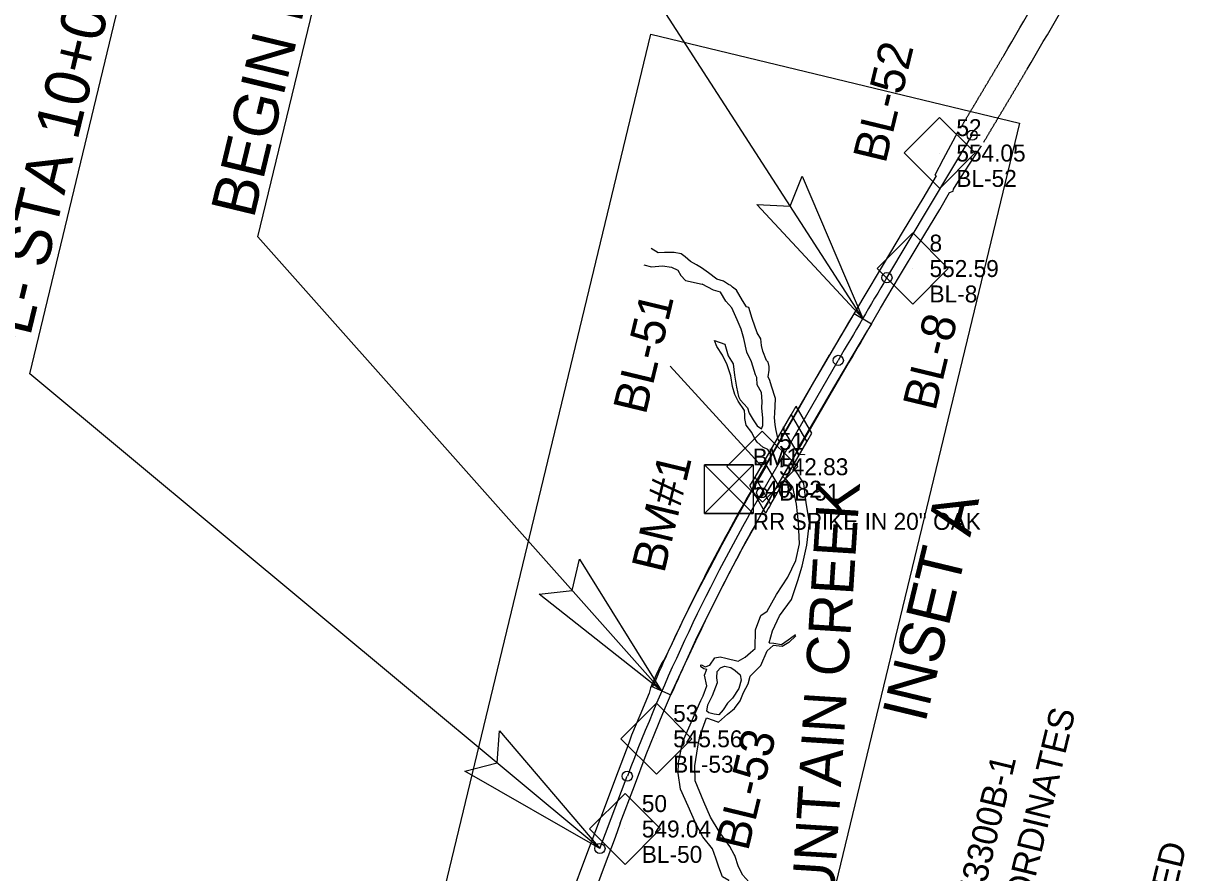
# Model space of a CAD drawing. Extents: x 1649669 to 1659218, y 588594 to 607900.
# Drawn here: x 1652859 to 1654231, y 597539 to 598543 of the extents above; entities that cross this region are included whole.
import ezdxf

# ---------------------------------------------------------------- set-up
doc = ezdxf.new("R2010")
doc.units = 0
for name, color, linetype in [('CTL Bench Mark CELL', 7, 'Continuous'), ('CTL Bench Mark Cogo Comment', 7, 'Continuous'), ('CTL Bench Mark Cogo Elevation', 7, 'Continuous'), ('CTL Bench Mark Cogo Number', 7, 'Continuous'), ('CTL Bench Mark Text', 7, 'Continuous'), ('CTL NGS Horizontal Text', 7, 'Continuous'), ('CTL Supplemental Horizontal and Vertical CELL', 7, 'Continuous'), ('CTL Supplemental Horizontal and Vertical Cogo Comment', 7, 'Continuous'), ('CTL Supplemental Horizontal and Vertical Cogo Elevation', 7, 'Continuous'), ('CTL Supplemental Horizontal and Vertical Cogo Number', 7, 'Continuous'), ('CTL Supplemental Horizontal and Vertical Leader', 7, 'Continuous'), ('CTL Supplemental Horizontal and Vertical Text', 7, 'Continuous'), ('Default', 7, 'Continuous'), ('Exist Hydro Jurisdictional Stream or Body of Water', 7, 'Continuous'), ('Exist Hydro Stream or Body of Water', 7, 'Continuous'), ('Exist Roads EOP', 7, 'Continuous'), ('Exist Structure Major Bridge WW', 7, 'Continuous'), ('Exist Structure Major Deck Tunnel Box Culvert', 7, 'Continuous'), ('Old_Level_20', 7, 'Continuous'), ('Old_Level_3', 7, 'Continuous'), ('Prop EOT', 7, 'Continuous'), ('Prop Horizontal Alignment', 7, 'Continuous'), ('Prop Horizontal Alignment Station Label', 7, 'Continuous'), ('Prop Terminator CELL', 7, 'Continuous'), ('Sheet Cutting Line CELL', 7, 'Continuous'), ('Sheet Data Field CELL', 7, 'Continuous')]:
    doc.layers.add(name, color=color, linetype=linetype)

msp = doc.modelspace()

# ---------------------------------------------------------------- linework, layer by layer
at = {"layer": 'CTL Bench Mark CELL'}
msp.add_line((1653692.9, 597992.3), (1653692.9, 597992.3), dxfattribs=at)
msp.add_lwpolyline([(1653664.1, 598021), (1653721.6, 598021), (1653721.6, 597963.5), (1653664.1, 597963.5)], close=True, dxfattribs=at)
for points in [[(1653721.6, 598021), (1653664.1, 597963.5), (1653692.9, 597992.2), (1653721.6, 597963.5), (1653664.1, 598021)], [(1653692.9, 597992.2), (1653721.6, 598021), (1653664.1, 598021), (1653692.9, 597992.2)], [(1653692.9, 597992.2), (1653664.1, 597963.5), (1653721.6, 597963.5), (1653692.9, 597992.2)]]:
    msp.add_lwpolyline(points, dxfattribs=at)
at = {"layer": 'CTL Supplemental Horizontal and Vertical CELL'}
for p, q in [((1653941.5, 598389.3), (1653941.5, 598389.3)), ((1653909.8, 598252.9), (1653909.8, 598252.9)), ((1653732.1, 598018.8), (1653732.1, 598018.8)), ((1653607, 597697.5), (1653607, 597697.5)), ((1653570, 597591), (1653570, 597591))]:
    msp.add_line(p, q, dxfattribs=at)
for points in [[(1653899.8, 598389.5), (1653941.7, 598431.4), (1653983.7, 598389.4), (1653941.8, 598347.5)], [(1653868, 598253), (1653910, 598295), (1653952, 598253), (1653910, 598211)], [(1653690.4, 598018.9), (1653732.3, 598060.9), (1653774.3, 598018.9), (1653732.4, 597976.9)], [(1653565.3, 597697.6), (1653607.2, 597739.6), (1653649.2, 597697.6), (1653607.3, 597655.6)], [(1653528.3, 597591.1), (1653570.2, 597633), (1653612.2, 597591), (1653570.3, 597549.1)]]:
    msp.add_lwpolyline(points, close=True, dxfattribs=at)
at = {"layer": 'CTL Supplemental Horizontal and Vertical Leader'}
msp.add_lwpolyline([(1653732.1, 598018.8), (1653623.5, 598137.5)], dxfattribs=at)
at = {"layer": 'Default'}
for p, q in [((1653136.5, 598290.4), (1653329, 599087.7)), ((1653850.9, 598193.8), (1653425.8, 598852.2)), ((1652867, 598128.7), (1653023.1, 598775.4)), ((1653612.7, 597754.5), (1653136.5, 598290.4)), ((1653540.5, 597567.9), (1652867, 598128.7))]:
    msp.add_line(p, q, dxfattribs=at)
at = {"layer": 'Exist Hydro Jurisdictional Stream or Body of Water'}
for points in [[(1653668.8, 598247.7), (1653660.4, 598253.7), (1653654.5, 598257.1), (1653647.4, 598261.4), (1653641.1, 598266.7), (1653636.3, 598270.3), (1653628.2, 598271.7), (1653616.9, 598271.7), (1653609.4, 598271.5), (1653601.2, 598276.4)], [(1653592.2, 598257.3), (1653601.6, 598254.8), (1653614.5, 598256.1), (1653625.2, 598254.5), (1653632.5, 598251.1), (1653636.2, 598244.7), (1653641.6, 598238.9), (1653661.4, 598234.3)], [(1653739.3, 598142.3), (1653737.1, 598144.2), (1653732.8, 598155.3), (1653731.3, 598161.9), (1653730.4, 598169.8), (1653726.1, 598176.9), (1653720.3, 598193.7), (1653716.5, 598207), (1653713.8, 598207.6), (1653708.8, 598215.1), (1653701.7, 598227.2), (1653697.2, 598231), (1653695.2, 598232.9), (1653692.2, 598233.9), (1653686.5, 598237.8), (1653678.5, 598240.3), (1653668.8, 598247.7)], [(1653724.3, 598127.5), (1653719.5, 598142.7), (1653714.2, 598154.2), (1653710.3, 598170.1), (1653707.2, 598181.3), (1653702.5, 598192.5), (1653696.3, 598206.5), (1653689.4, 598214.3), (1653683.1, 598225.1), (1653674.5, 598227.4), (1653661.4, 598234.3)], [(1653714.7, 598088.5), (1653716.6, 598082.1), (1653721.3, 598074.1), (1653726.4, 598067), (1653731.2, 598063.6), (1653732.9, 598067.7), (1653733, 598076.1), (1653731.6, 598088.3), (1653732.1, 598095.9), (1653731.5, 598106.6), (1653726.4, 598115.7), (1653725.8, 598124.4), (1653724.3, 598127.5)], [(1653752.6, 598048.3), (1653751.1, 598051), (1653748.6, 598061.5), (1653747.5, 598068.2), (1653746.7, 598076.9), (1653747.2, 598081.7), (1653748, 598099.4), (1653743.3, 598114.1), (1653741.1, 598120.6)], [(1653743.2, 598031.5), (1653741.8, 598033.9), (1653738.9, 598039), (1653733.1, 598041.9), (1653726.3, 598048), (1653722.6, 598053.2), (1653719.9, 598059.4), (1653713.2, 598067.9), (1653711.6, 598075.7), (1653711.8, 598079.7), (1653711.1, 598085.3)], [(1653740.5, 597810.8), (1653744.5, 597825.2), (1653752.7, 597842.9), (1653766.9, 597862.1), (1653774.2, 597884.6), (1653779.2, 597901.2), (1653784.8, 597926.2), (1653788.2, 597953), (1653784.2, 597976.2), (1653781.5, 597999.1), (1653770, 598016.7), (1653766, 598023.9)], [(1653703.8, 597789.2), (1653712, 597793.9), (1653718.2, 597799.4), (1653723.7, 597804.1), (1653724.2, 597826.1), (1653730.4, 597843.3), (1653737.9, 597848.4), (1653749, 597867.9), (1653762.5, 597888.2), (1653771.7, 597908), (1653776.1, 597927.8), (1653775.2, 597952.4), (1653772.6, 597974.7), (1653768.4, 597994.5), (1653761, 598003.5), (1653757.3, 598006.3), (1653756.6, 598007.5)], [(1653717.8, 597771.3), (1653730.5, 597783.9), (1653737.9, 597801.3)], [(1653659.4, 597784.6), (1653659.2, 597783.4), (1653663.1, 597780.7), (1653666.7, 597779.7)], [(1653659.4, 597784.6), (1653660.3, 597784.7), (1653664.8, 597782.3), (1653670.2, 597784.3)], [(1653670.2, 597784.3), (1653676.3, 597793), (1653682.4, 597794.4), (1653689.4, 597792.6), (1653703.8, 597789.2)], [(1653638.4, 597694.5), (1653659.6, 597742.6), (1653662.6, 597748.1), (1653666.7, 597759.9), (1653664.1, 597772.6), (1653666.7, 597779.7)], [(1653666.8, 597730.2), (1653668.1, 597737.6), (1653673.5, 597748.5), (1653679.4, 597764.1), (1653678.5, 597769.4), (1653679.1, 597776.9), (1653682.8, 597781.3), (1653687.7, 597783.3), (1653695.3, 597781.9), (1653700.4, 597778.2), (1653706.2, 597773.2)], [(1653693.8, 597570.3), (1653681.5, 597588.1), (1653671, 597605.1), (1653663.1, 597623.2), (1653653, 597647.9), (1653652.7, 597665.5), (1653656.2, 597688.2), (1653658.3, 597700.5), (1653666.3, 597722.4)], [(1653673.4, 597567.6), (1653662.2, 597581.7), (1653653.5, 597598.1), (1653644.9, 597618), (1653635.8, 597638.1), (1653632.9, 597656.9), (1653633.3, 597669.7), (1653638.4, 597694.5)], [(1653730.3, 597338.1), (1653733.3, 597360.2), (1653735.6, 597380.6), (1653726.8, 597413.4), (1653724.7, 597422.1), (1653718.3, 597439.8), (1653719.4, 597456.6), (1653714.6, 597471.9), (1653709.4, 597485), (1653703.2, 597498.6), (1653701.5, 597506), (1653695.8, 597517.3), (1653692.9, 597530.2), (1653685.3, 597534.3), (1653681, 597546), (1653677.2, 597556.7), (1653673.4, 597567.6)], [(1653748.4, 597343.1), (1653752.9, 597375.2), (1653752.5, 597388.1), (1653747.3, 597414.1), (1653745.8, 597424.3), (1653743.5, 597437.2), (1653740.3, 597449.2), (1653740, 597455.8), (1653734.8, 597464.4), (1653730.6, 597471.8), (1653727.7, 597497.5), (1653726.4, 597508.9), (1653723.9, 597520.6), (1653716.2, 597528.4), (1653709.3, 597536.5), (1653704.3, 597546.2), (1653699.9, 597559.6), (1653699.1, 597561), (1653693.8, 597570.3)]]:
    msp.add_lwpolyline(points, dxfattribs=at)
at = {"layer": 'Exist Hydro Stream or Body of Water'}
for points in [[(1653676, 598167.9), (1653688.1, 598163.7), (1653691.8, 598149.9), (1653698, 598140.2), (1653699.4, 598127), (1653702, 598112.9), (1653704.1, 598101.8), (1653706.2, 598098), (1653714.7, 598088.5)], [(1653711.1, 598085.3), (1653703.7, 598096.4), (1653699.8, 598104.3), (1653697.2, 598113.7), (1653695.1, 598126), (1653690.7, 598139.3), (1653685.1, 598150.4), (1653678.4, 598160.7), (1653676, 598167.9)], [(1653741.1, 598120.6), (1653739.1, 598125.1), (1653740.2, 598132.9), (1653740.3, 598137.3), (1653739.3, 598142.3)], [(1653771.8, 597819.1), (1653763.7, 597811.4), (1653755.8, 597806.7), (1653745.1, 597807.8), (1653737.9, 597801.3)], [(1653740.5, 597810.8), (1653745.8, 597810.3), (1653755, 597809), (1653762.9, 597814.5), (1653771.5, 597820.5)], [(1653706.2, 597773.2), (1653707.3, 597766.6), (1653704.4, 597757.1), (1653696.9, 597745.3), (1653691.1, 597739.4), (1653685.9, 597731.6), (1653681.1, 597725.9), (1653675.3, 597726.5), (1653669.2, 597728.2), (1653666.8, 597730.2)], [(1653699.3, 597733.4), (1653706.2, 597742.2), (1653709.9, 597752.2), (1653715.6, 597762.4), (1653717.8, 597771.3)], [(1653666.3, 597722.4), (1653674.4, 597719.5), (1653680.7, 597717.3), (1653691.1, 597726.4), (1653697, 597731.5), (1653699.3, 597733.4)]]:
    msp.add_lwpolyline(points, dxfattribs=at)
at = {"layer": 'Exist Roads EOP'}
for points in [[(1653963.2, 598414.5), (1653946.1, 598382.2), (1653936.1, 598363.3), (1653937.6, 598362.4), (1653921.9, 598335.5), (1653898.6, 598297.3), (1653875, 598257.8), (1653851, 598217.6), (1653836.5, 598192.6), (1653818.8, 598162.7), (1653796.3, 598124.5), (1653774.3, 598085.7), (1653760, 598060.8), (1653759, 598059.6)], [(1653773.1, 598036.4), (1653773.1, 598036.7), (1653772.7, 598037.2), (1653794.4, 598073.8), (1653816.9, 598112.3), (1653839.5, 598150.8), (1653856.9, 598180.3), (1653871.8, 598206), (1653894.4, 598243.9), (1653917.4, 598282.6), (1653942, 598322.8), (1653953.2, 598342.5), (1653957.8, 598344.4), (1653958, 598346.5), (1653959.3, 598348.6), (1653971.1, 598367.1), (1653991, 598397.8)], [(1653736.9, 598020.2), (1653736.6, 598019), (1653719.2, 597989.2), (1653700.6, 597956.1), (1653684.6, 597926.7), (1653670.3, 597899.6), (1653655.3, 597871), (1653640.4, 597841.4), (1653625.6, 597809.6), (1653616.4, 597790.9), (1653615.5, 597790.1), (1653613.4, 597786.4), (1653606.9, 597772.9), (1653600.4, 597757.8), (1653598.6, 597751.5), (1653587.8, 597725.2), (1653577.7, 597701.6), (1653574.8, 597692.2), (1653559, 597651), (1653542.1, 597605.7)], [(1653564.5, 597597.7), (1653581.2, 597642.1), (1653595.3, 597679), (1653605.2, 597704.2), (1653614.9, 597727.4), (1653626, 597753.2), (1653641, 597786.5), (1653655.9, 597818.7), (1653671.7, 597850.9), (1653688.4, 597883.5), (1653707.1, 597919), (1653720.7, 597943.7), (1653734.9, 597970.1), (1653749.8, 597996.4), (1653750.8, 597997.3)], [(1653472.3, 597421.4), (1653481.4, 597445.1), (1653491.5, 597471.6), (1653506.4, 597511.5), (1653524.9, 597561.2), (1653542.1, 597605.7)], [(1653564.5, 597597.7), (1653558.4, 597580.8), (1653545.6, 597546.8), (1653529.7, 597504), (1653515.6, 597467.4), (1653493.8, 597408.8)]]:
    msp.add_lwpolyline(points, dxfattribs=at)
for radius in [8984, 9016]:
    msp.add_arc((1646280.4, 603070.7), radius, 329.45173, 330.4149, dxfattribs=at)
for points in [[(1653966.3, 598418.6), (1653967, 598419.8), (1653967.7, 598420.9), (1653968.4, 598422.1), (1653969.1, 598423.2), (1653969.8, 598424.4), (1653970.5, 598425.6), (1653971.2, 598426.7), (1653971.9, 598427.9), (1653972.6, 598429), (1653973.3, 598430.2), (1653974, 598431.4), (1653974.7, 598432.5), (1653975.4, 598433.7), (1653976.1, 598434.8), (1653976.7, 598436), (1653977.4, 598437.2), (1653978.1, 598438.3), (1653978.8, 598439.5), (1653979.5, 598440.6), (1653980.2, 598441.8), (1653980.9, 598443), (1653981.6, 598444.1), (1653982.3, 598445.3), (1653983, 598446.4), (1653983.7, 598447.6), (1653984.4, 598448.8), (1653985.1, 598449.9), (1653985.7, 598451.1), (1653986.4, 598452.2), (1653987.1, 598453.4), (1653987.8, 598454.6), (1653988.5, 598455.7), (1653989.2, 598456.9), (1653989.9, 598458), (1653990.6, 598459.2), (1653991.3, 598460.4), (1653992, 598461.5), (1653992.7, 598462.7), (1653993.4, 598463.8), (1653994, 598465), (1653994.7, 598466.2), (1653995.4, 598467.3), (1653996.1, 598468.5), (1653996.8, 598469.6), (1653997.5, 598470.8), (1653998.2, 598472), (1653998.9, 598473.1), (1653999.6, 598474.3), (1654000.3, 598475.4), (1654000.9, 598476.6), (1654001.6, 598477.8), (1654002.3, 598478.9), (1654003, 598480.1), (1654003.7, 598481.2), (1654004.4, 598482.4), (1654005.1, 598483.6), (1654005.8, 598484.7), (1654006.5, 598485.9), (1654007.1, 598487), (1654007.8, 598488.2), (1654008.5, 598489.4), (1654009.2, 598490.5), (1654009.9, 598491.7), (1654010.6, 598492.8), (1654011.3, 598494), (1654012, 598495.2), (1654012.6, 598496.3), (1654013.3, 598497.5), (1654014, 598498.6), (1654014.7, 598499.8), (1654015.4, 598501), (1654016.1, 598502.1), (1654016.8, 598503.3), (1654017.4, 598504.5)], [(1653993.8, 598402.2), (1653994.5, 598403.3), (1653995.2, 598404.5), (1653995.9, 598405.7), (1653996.6, 598406.8), (1653997.3, 598408), (1653998, 598409.1), (1653998.7, 598410.3), (1653999.4, 598411.5), (1654000.1, 598412.6), (1654000.7, 598413.8), (1654001.4, 598414.9), (1654002.1, 598416.1), (1654002.8, 598417.3), (1654003.5, 598418.4), (1654004.2, 598419.6), (1654004.9, 598420.7), (1654005.6, 598421.9), (1654006.3, 598423.1), (1654007, 598424.2), (1654007.7, 598425.4), (1654008.4, 598426.5), (1654009.1, 598427.7), (1654009.8, 598428.9), (1654010.5, 598430), (1654011.1, 598431.2), (1654011.8, 598432.4), (1654012.5, 598433.5), (1654013.2, 598434.7), (1654013.9, 598435.8), (1654014.6, 598437), (1654015.3, 598438.2), (1654016, 598439.3), (1654016.7, 598440.5), (1654017.4, 598441.6), (1654018.1, 598442.8), (1654018.8, 598444), (1654019.5, 598445.1), (1654020.2, 598446.3), (1654020.8, 598447.5), (1654021.5, 598448.6), (1654022.2, 598449.8), (1654022.9, 598450.9), (1654023.6, 598452.1), (1654024.3, 598453.3), (1654025, 598454.4), (1654025.7, 598455.6), (1654026.4, 598456.8), (1654027.1, 598457.9), (1654027.8, 598459.1), (1654028.5, 598460.2), (1654029.1, 598461.4), (1654029.8, 598462.6), (1654030.5, 598463.7), (1654031.2, 598464.9), (1654031.9, 598466.1), (1654032.6, 598467.2), (1654033.3, 598468.4), (1654034, 598469.6), (1654034.7, 598470.7), (1654035.4, 598471.9), (1654036, 598473), (1654036.7, 598474.2), (1654037.4, 598475.4), (1654038.1, 598476.5), (1654038.8, 598477.7), (1654039.5, 598478.9), (1654040.2, 598480), (1654040.9, 598481.2), (1654041.6, 598482.4), (1654042.3, 598483.5), (1654042.9, 598484.7), (1654043.6, 598485.9), (1654044.3, 598487), (1654045, 598488.2)]]:
    msp.add_spline(points, degree=3, dxfattribs=at)
at = {"layer": 'Exist Structure Major Bridge WW'}
for points in [[(1653758.6, 598061.2), (1653757.3, 598063.4), (1653756.9, 598063.3), (1653758.1, 598060.9), (1653773.6, 598035.5)], [(1653757.4, 598063.3), (1653757.2, 598066.1), (1653757.6, 598066.1), (1653757.9, 598062.5)], [(1653773.9, 598035.5), (1653775.7, 598032.6), (1653775.4, 598032.4), (1653773.6, 598035.5)], [(1653775, 598033.7), (1653782.1, 598033.4), (1653782, 598033), (1653775.2, 598033.2)], [(1653735.1, 598023.3), (1653729, 598024), (1653728.8, 598023.7), (1653735.3, 598022.9)], [(1653736.3, 598021.1), (1653734.8, 598023.9), (1653735, 598024), (1653736.4, 598021.2)], [(1653736.4, 598021.2), (1653751.9, 597995.6), (1653753.4, 597993.3), (1653753.2, 597993.1), (1653751.7, 597995.4)], [(1653752.3, 597994.4), (1653752.9, 597986.7), (1653753.5, 597986.9), (1653752.8, 597993.7)]]:
    msp.add_lwpolyline(points, dxfattribs=at)
at = {"layer": 'Exist Structure Major Deck Tunnel Box Culvert'}
for points in [[(1653758.8, 598059.4), (1653737, 598020.6)], [(1653750.8, 597997.3), (1653773.1, 598036.4)]]:
    msp.add_lwpolyline(points, dxfattribs=at)
at = {"layer": 'Old_Level_3'}
for p, q in [((1653766.3, 598080.1), (1653772.3, 598090.5)), ((1653790.8, 598058.5), (1653772.3, 598090.5)), ((1653723.8, 598006.5), (1653766.3, 598080.1)), ((1653766.3, 598080.1), (1653784.8, 598048.1)), ((1653742.2, 597974.5), (1653784.8, 598048.1)), ((1653784.8, 598048.1), (1653790.8, 598058.5)), ((1653717.7, 597996.1), (1653723.8, 598006.5)), ((1653742.2, 597974.4), (1653723.8, 598006.5)), ((1653717.7, 597996.1), (1653736.2, 597964.1))]:
    msp.add_line(p, q, dxfattribs=at)
msp.add_arc((1655696.4, 596851.2), 2254, 150.1078, 150.4141, dxfattribs=at)
at = {"layer": 'Prop EOT'}
for p, q in [((1653840.7, 598199.8), (1653861.2, 598187.7)), ((1653721.2, 597994.1), (1653811.7, 598150.4)), ((1653741.9, 597982), (1653832.4, 598138.4)), ((1653601.1, 597759.5), (1653624.4, 597749.4))]:
    msp.add_line(p, q, dxfattribs=at)
for centre, radius, start, end in [((1660732.4, 594113.8), 8012, 149.3372, 149.69477), ((1660747.3, 594139.2), 7988, 149.54773, 149.90637), ((1660746.4, 594137.8), 8012, 149.89309, 149.9451), ((1660746.4, 594137.8), 7988, 149.89416, 149.9451), ((1655696.4, 596851.2), 2282, 149.9451, 155.3066), ((1655696.4, 596851.2), 2258, 149.9451, 155.2932), ((1655696.4, 596851.2), 2282, 155.3066, 156.5621), ((1655690.5, 596838.1), 2258.2, 154.9314, 156.2002)]:
    msp.add_arc(centre, radius, start, end, dxfattribs=at)
at = {"layer": 'Prop Horizontal Alignment'}
for p, q in [((1653879.5, 598242.1), (1653980.1, 598410.4)), ((1653731.6, 597988), (1653822, 598144.4)), ((1653540.5, 597567.9), (1653572.8, 597653.4))]:
    msp.add_line(p, q, dxfattribs=at)
for centre, radius, start, end in [((1660746.4, 594137.8), 8000, 149.13342, 149.9451), ((1655696.4, 596851.2), 2270, 149.9451, 159.3037)]:
    msp.add_arc(centre, radius, start, end, dxfattribs=at)
at = {"layer": 'Prop Horizontal Alignment Station Label'}
for centre in [(1653980.1, 598410.4), (1653879.5, 598242.1), (1653822, 598144.4), (1653731.6, 597988), (1653572.8, 597653.4), (1653540.5, 597567.9)]:
    msp.add_circle(centre, 6, dxfattribs=at)
at = {"layer": 'Prop Terminator CELL'}
for points in [[(1653779.3, 598361.8), (1653850.9, 598193.8), (1653725.9, 598328.5), (1653765.2, 598326.5)], [(1653516.4, 597909.6), (1653612.7, 597754.5), (1653468.6, 597868.5), (1653507.8, 597872.6)], [(1653422, 597706.9), (1653540.5, 597567.9), (1653381, 597659.1), (1653419.1, 597669)]]:
    msp.add_lwpolyline(points, close=True, dxfattribs=at)
at = {"layer": 'Sheet Cutting Line CELL'}
msp.add_lwpolyline([(1653333.2, 597421.3), (1653600.8, 598529.7), (1654035.9, 598424.7), (1653768.3, 597316.3)], close=True, dxfattribs=at)

# ---------------------------------------------------------------- texts
at = {"layer": 'CTL Bench Mark Cogo Comment'}
msp.add_text('RR SPIKE IN 20" OAK', height=20, dxfattribs=at).set_placement((1653720.9, 597944.3))
at = {"layer": 'CTL Bench Mark Cogo Elevation'}
msp.add_text('540.82', height=20, dxfattribs=at).set_placement((1653720.9, 597982.3))
at = {"layer": 'CTL Bench Mark Cogo Number'}
msp.add_text('BM1', height=20, dxfattribs=at).set_placement((1653720.9, 598020.3))
at = {"layer": 'CTL Bench Mark Text'}
msp.add_text('BM#1', height=40, rotation=76.4261, dxfattribs=at).set_placement((1653616.3, 597892))
at = {"layer": 'CTL NGS Horizontal Text'}
for s, p in [('LOCALIZED PROJECT COORDINATES', (1653931.9, 597023.7)), ('NCDOT GPS STATION U3300B-1', (1653887.9, 597075.7)), ('ELEV= 565.61  - REVISED', (1654120.6, 597102.3))]:
    msp.add_text(s, height=30, rotation=76.4261, dxfattribs=at).set_placement(p)
at = {"layer": 'CTL Supplemental Horizontal and Vertical Cogo Comment'}
for s, p in [('BL-52', (1653961.5, 598349.3)), ('BL-8', (1653929.8, 598212.9)), ('BL-51', (1653752.1, 597978.8)), ('BL-53', (1653627, 597657.5)), ('BL-50', (1653590, 597551))]:
    msp.add_text(s, height=20, dxfattribs=at).set_placement(p)
at = {"layer": 'CTL Supplemental Horizontal and Vertical Cogo Elevation'}
for s, p in [('554.05', (1653961.5, 598379.3)), ('552.59', (1653929.8, 598242.9)), ('542.83', (1653752.1, 598008.8)), ('545.56', (1653627, 597687.5)), ('549.04', (1653590, 597581))]:
    msp.add_text(s, height=20, dxfattribs=at).set_placement(p)
at = {"layer": 'CTL Supplemental Horizontal and Vertical Cogo Number'}
for s, p in [('52', (1653961.5, 598409.3)), ('8', (1653929.8, 598272.9)), ('51', (1653752.1, 598038.8)), ('53', (1653627, 597717.5)), ('50', (1653590, 597611))]:
    msp.add_text(s, height=20, dxfattribs=at).set_placement(p)
at = {"layer": 'CTL Supplemental Horizontal and Vertical Text'}
for s, p in [('BL-52', (1653877.8, 598375.9)), ('BL-51', (1653594.5, 598079.2)), ('BL-8', (1653936.6, 598083.6)), ('BL-53', (1653715.4, 597563.9))]:
    msp.add_text(s, height=40, rotation=76.4261, dxfattribs=at).set_placement(p)
at = {"layer": 'Old_Level_20'}
msp.add_text('LITTLE MOUNTAIN CREEK', height=50, rotation=86.3815, dxfattribs=at).set_placement((1653794.6, 597158.1))
at = {"layer": 'Sheet Data Field CELL'}
for s, height, p in [('BEGIN PROJECT B-5137', 52.501, (1653131.5, 598310.8)), ('-L- STA 10+00.00', 52.501, (1652861.9, 598149.1)), ('INSET A', 52.5, (1653924.6, 597715))]:
    msp.add_text(s, height=height, rotation=76.4261, dxfattribs=at).set_placement(p)

doc.saveas('drawing.dxf')
